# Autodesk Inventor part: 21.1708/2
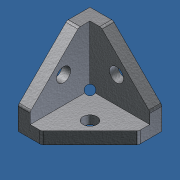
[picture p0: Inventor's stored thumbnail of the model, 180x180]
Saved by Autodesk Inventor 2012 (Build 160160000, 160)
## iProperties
Created: 2007-01
Part Number: 21.1708/2
Document SubType Name: Modeling
Designer: Andy Moles
Material: Aluminum-6061
Density: 2.71 g/cm^3
Stock Number: Angle 45 Deg Al Casting
Author: Andy Moles
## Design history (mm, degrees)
sketch "Sketch1"
  geometry: L1 (0, 0)-(0, -42); L2 (0, 0)-(42, 0); L3 (0, -42)-(13.5, -42); L4 (42, 0)-(42, -13.5); L5 (13.5, -42)-(42, -13.5)
  constraints: 10 end point, 2 perpendicular, 1 parallel, 1 vertical
  dimensions: "d0" = 42 distance of L1.start L1.end; "d1" = 42 distance of L1.start L2.end; "d2" = 13.5 distance of L1.end L3.end; "d3" = 13.5 distance of L2.end L4.end (= d2)
extrude "Extrusion1" new body sketch "Sketch1" distance "d4" = 42; taper "d5" = 0 deg
sketch "Sketch2"
  geometry: L1 (0, 0)-(42, 0) reference; L2 (0, -42)-(0, 0) reference; L3 (7, -7)-(57.245, -7); L4 (57.245, -7)-(57.245, -50.91); L5 (57.245, -50.91)-(7, -50.91); L6 (7, -50.91)-(7, -7)
  constraints: 8 end point, 2 parallel, 1 horizontal, 1 perpendicular
  dimensions: "d6" = 7 distance between parallel lines of L3 L1; "d7" = 7 distance between parallel lines of L6 L2
extrude "Extrusion2" cut sketch "Sketch2" distance "d8" = 35; taper "d9" = 0 deg
sketch "Sketch3"
  geometry: L1 (42, 0)-(42, 42) reference; L2 (0, 42)-(42, 42) reference; L3 (0, 0)-(42, 0) reference; L4 (42, 28.5)-(13.5, 0); L5 (13.5, 0)-(42, 0); L6 (42, 0)-(42, 28.5)
  constraints: 6 end point, 2 collinear, 2 point on line
  dimensions: "d10" = 13.5 distance from line of L4.start L2; "d11" = 13.5 distance of L3.start L4.end (= d10)
extrude "Extrusion3" cut sketch "Sketch3" stored distance "d12" = 35; taper "d13" = 0 deg
sketch "Sketch4"
  geometry: L1 (0, -42)-(42, -42) reference; L2 (42, 0)-(42, -42) reference; L3 (42, 0)-(0, 0) reference; L4 (13.5, -42)-(42, -13.5); L5 (42, -13.5)-(42, -42); L6 (42, -42)-(13.5, -42)
  constraints: 6 end point, 2 collinear, 2 point on line
  dimensions: "d14" = 13.5 distance from line of L4.end L3 (= d15); "d15" = 13.5 distance of L1.start L4.start
extrude "Extrusion4" cut sketch "Sketch4" distance "d16" = 35; taper "d17" = 0 deg
hole "Hole1" diameter "d20" = 8.2; stored, may be unused: countersink angle "d24" = 90 deg, drill point angle "d26" = 118 deg; dims "d18" = 22.5, "d19" = 22.5, "d21" = 6, "d22" = 4, "d23" = 2, "d25" = 8
hole "Hole2" diameter "d29" = 8.2; stored, may be unused: countersink angle "d33" = 90 deg, drill point angle "d35" = 118 deg; dims "d27" = 22.5, "d28" = 22.5, "d30" = 6, "d31" = 4, "d32" = 2, "d34" = 8
hole "Hole3" diameter "d38" = 8.2; stored, may be unused: countersink angle "d42" = 90 deg, drill point angle "d44" = 118 deg; dims "d36" = 22.5, "d37" = 22.5, "d39" = 6, "d40" = 4, "d41" = 2, "d43" = 8
sketch "Sketch5"
  geometry: L1 (29.25, 29.5)-(29.25, 19.5); L2 (15.75, 29.5)-(15.75, 19.5); C1 r 4.1 at (22.5, 19.5) reference; A1 r 6.75 centre (22.5, 19.5) between (15.75, 19.5) and (29.25, 19.5); A2 r 6.75 centre (22.5, 29.5) between (29.25, 29.5) and (15.75, 29.5)
  constraints: 4 end point, 4 point on circle, 4 tangent, 2 centre point, 1 coincident, 1 vertical alignment
  dimensions: "d45" = 13.5 diameter of A1; "d46" = 13.5 diameter of A2; "d47" = 23.5 dimension on A1 A2
extrude "Extrusion5" cut sketch "Sketch5" distance "d48" = 2; taper "d49" = 0 deg
sketch "Sketch6"
  geometry: L1 (29.25, -12.5)-(29.25, -22.5); L2 (15.75, -12.5)-(15.75, -22.5); C1 r 4.1 at (22.5, -22.5) reference; A1 r 6.75 centre (22.5, -22.5) between (15.75, -22.5) and (29.25, -22.5); A2 r 6.75 centre (22.5, -12.5) between (29.25, -12.5) and (15.75, -12.5)
  constraints: 4 end point, 4 point on circle, 3 tangent, 2 centre point, 1 coincident, 1 parallel, 1 vertical alignment
  dimensions: "d50" = 13.5 diameter of A1; "d51" = 13.5 diameter of A2; "d52" = 23.5 dimension on A1 A2
extrude "Extrusion6" cut sketch "Sketch6" distance "d53" = 2; taper "d54" = 0 deg
sketch "Sketch7"
  geometry: L1 (0, -42)-(-13.5, -42) reference; L2 (-22.5, -22.5)-(-29.25, -22.5); L3 (-22.5, -22.5)-(-5.75, -22.5); L4 (-22.516, -15.75)-(-12.516, -15.727); L5 (-12.484, -29.227)-(-22.484, -29.25); C1 r 4.1 at (-22.5, -22.5) reference; A1 r 6.75 centre (-22.5, -22.5) between (-22.516, -15.75) and (-22.484, -29.25); A2 r 6.75 centre (-12.5, -22.477) between (-12.484, -29.227) and (-12.516, -15.727)
  constraints: 8 end point, 6 point on circle, 3 tangent, 2 centre point, 2 parallel, 1 coincident, 1 collinear
  dimensions: "d55" = 13.5 diameter of A1; "d56" = 13.5 diameter of A2; "d57" = 23.5 distance of L3.end L2.end
extrude "Extrusion7" cut sketch "Sketch7" distance "d58" = 2; taper "d59" = 0 deg
workplane "Work Plane1"
sketch "Sketch8"
  geometry: L1 (29.698, 17.146)-(4.95, 2.858) reference; L2 (54.447, 2.858)-(29.698, 17.146) reference; L3 (29.698, 45.724)-(29.698, 17.146) reference; C1 r 2.45 at (29.698, 17.146)
  constraints: 1 centre point, 1 coincident
  dimensions: "d60" = 4.9 diameter of C1
extrude "Extrusion8" cut sketch "Sketch8" stored distance "d61" = 10; taper "d62" = 0 deg
fillet "Fillet1" dims "d63" = 2
body "Solid1"
